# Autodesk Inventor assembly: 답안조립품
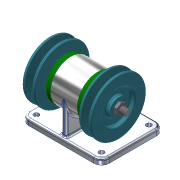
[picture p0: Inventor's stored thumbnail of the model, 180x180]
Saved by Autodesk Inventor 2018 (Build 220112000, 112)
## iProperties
Created: 2019-09
Part Number: 답안조립품
Material: 일반
Document SubType Name: Assembly
Designer: USER
Author: USER
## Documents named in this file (10)
- C:\Users\USER\Desktop\490904V1047\답안조립품.iam
- C:\Users\USER\Desktop\490904V1047\1-본체.ipt
- C:\Users\USER\Desktop\490904V1047\오일 실 17 30 5.ipt
- C:\Users\USER\Desktop\490904V1047\축.ipt
- C:\Users\USER\Desktop\490904V1047\커버.ipt
- C:\Users\USER\Desktop\490904V1047\키 5 x 5 x 12.ipt
- C:\Users\USER\Desktop\490904V1047\V-벨트풀리.ipt
- C:\Users\USER\Desktop\490904V1047\너트 M10x1.ipt
- C:\Users\USER\Desktop\490904V1047\베어링 6004.ipt
- C:\Users\USER\Desktop\490904V1047\볼트 M4.ipt
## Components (3 placed, 2 different names)
1. 1-본체:1
2. V-벨트풀리:1
3. V-벨트풀리:2
## Named parameters: d11_d10 = 0
